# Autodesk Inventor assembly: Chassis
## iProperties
Created: 2011-01
Part Number: Chassis
Document SubType Name: Assembly
Designer: eric
Mass: 5425.4 g
Surface Area: 15287.7 cm^2
Volume: 5425.4 cm^3
Density: 1 g/cm^3
Author: eric
